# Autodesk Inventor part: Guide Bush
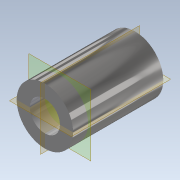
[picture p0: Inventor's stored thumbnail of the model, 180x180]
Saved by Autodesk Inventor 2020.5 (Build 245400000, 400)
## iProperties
LastFilename: FCG_Part.ipt
DataBaseUnit: MM
Created: 2023-05
Part Number: Guide Bush
Material: 250 Grade
Document SubType Name: Modeling
Designer: A. Bennett
Mass: 24.3943 g
Surface Area: 19.8706 cm^2
Volume: 3.03478 cm^3
Density: 8.03824 g/cm^3
Appearance: Steel
Author: A. Bennett
Revision Number: -
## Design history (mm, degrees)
sketch "Sketch10"
  geometry: C1 r 7.5 at (0, 0); 1 further point
  constraints: 1 centre point, 1 coincident
  dimensions: "d25" = 15 diameter of C1
extrude "Extrusion7" new body sketch "Sketch10" distance "d26" = 16; taper "d27" = 0 deg
sketch "Sketch11"
  geometry: C1 r 7.5 at (0, 0); 1 further point
  constraints: 1 centre point, 1 coincident
  dimensions: "d28" = 15 diameter of C1
extrude "Extrusion8" join sketch "Sketch11" distance "d29" = 4; taper "d30" = 0 deg
sketch "Sketch12"
  geometry: C1 r 7.5 at (0, 0); 1 further point
  constraints: 1 centre point, 1 coincident
  dimensions: "d31" = 15 diameter of C1
extrude "Extrusion9" join sketch "Sketch12" distance "d32" = 4; taper "d33" = 0 deg
sketch "Sketch13"
  geometry: C1 r 4 at (0, 0); 1 further point
  constraints: 1 centre point, 1 coincident
  dimensions: "d34" = 8 diameter of C1
extrude "Extrusion10" cut sketch "Sketch13" extent not by distance; stored distance "d35" = 0; taper "d36" = 0 deg
body "Solid7"
other parameters: "OD" = 1 [user parameter], "OAL" = 1 [user parameter]
